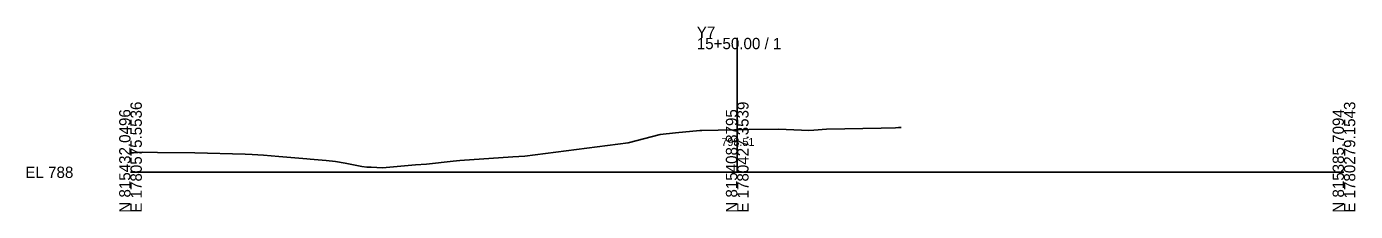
# Model space of a CAD drawing. Extents: x -26 to 2903, y -10 to 5536.
# Drawn here: x -25.7 to 302.8, y 5490.3 to 5536.1 of the extents above; entities that cross this region are included whole.
import ezdxf

# ---------------------------------------------------------------- set-up
doc = ezdxf.new("R2010")
doc.units = 0
for name, color, linetype in [('Exist Cross Section Cell', 7, 'Continuous'), ('Exist XS Center Line Elevation Label', 7, 'Continuous'), ('Exist XS Ground Line', 7, 'Continuous')]:
    doc.layers.add(name, color=color, linetype=linetype)

msp = doc.modelspace()

# ---------------------------------------------------------------- linework, layer by layer
at = {"layer": 'Exist Cross Section Cell'}
for p, q in [((150, 5500), (150, 5533.26)), ((0, 5500), (150, 5500)), ((150, 5500), (300, 5500))]:
    msp.add_line(p, q, dxfattribs=at)
at = {"layer": 'Exist XS Ground Line'}
for p, q in [((130.98, 5509.33), (134.78, 5509.72)), ((134.78, 5509.72), (140.78, 5510.31)), ((140.78, 5510.31), (141.25, 5510.32)), ((141.25, 5510.32), (149.33, 5510.5)), ((149.33, 5510.5), (150, 5510.51)), ((150, 5510.51), (152.87, 5510.55)), ((152.87, 5510.55), (160.24, 5510.68)), ((160.24, 5510.68), (165.92, 5510.38)), ((165.92, 5510.38), (167.67, 5510.37)), ((167.67, 5510.37), (168.93, 5510.39)), ((168.93, 5510.39), (172.09, 5510.69)), ((172.09, 5510.69), (185.55, 5510.89)), ((185.55, 5510.89), (189.12, 5511.03)), ((189.12, 5511.03), (189.85, 5511.06)), ((189.85, 5511.06), (190.54, 5511.09)), ((97.53, 5503.99), (123.01, 5507.3)), ((123.01, 5507.3), (130.98, 5509.33)), ((0, 5504.8), (0.76, 5504.84)), ((0.76, 5504.84), (2.92, 5504.94)), ((2.92, 5504.94), (6.71, 5504.9)), ((6.71, 5504.9), (15.94, 5504.78)), ((15.94, 5504.78), (28.34, 5504.5)), ((28.34, 5504.5), (30.08, 5504.41)), ((30.08, 5504.41), (32.88, 5504.25)), ((32.88, 5504.25), (36.64, 5503.94)), ((36.64, 5503.94), (43.61, 5503.34)), ((43.61, 5503.34), (44.44, 5503.27)), ((44.44, 5503.27), (48.34, 5502.89)), ((79.8, 5502.72), (81.43, 5502.93)), ((81.43, 5502.93), (94.51, 5503.86)), ((94.51, 5503.86), (97.53, 5503.99)), ((48.34, 5502.89), (50.67, 5502.66)), ((50.67, 5502.66), (53.09, 5502.23)), ((53.09, 5502.23), (57.21, 5501.46)), ((57.21, 5501.46), (58.39, 5501.24)), ((58.39, 5501.24), (59.49, 5501.23)), ((59.49, 5501.23), (62.33, 5501.13)), ((62.33, 5501.13), (70.47, 5501.82)), ((70.47, 5501.82), (73.14, 5502.04)), ((73.14, 5502.04), (79.8, 5502.72))]:
    msp.add_line(p, q, dxfattribs=at)

# ---------------------------------------------------------------- texts
at = {"layer": 'Exist Cross Section Cell'}
for s, p in [('Y7', (140, 5533.26)), ('15+50.00 / 1', (140, 5530.46)), ('EL 788', (-26, 5498.6))]:
    msp.add_text(s, height=2.8, dxfattribs=at).set_placement(p)
for s, p in [('E 1780575.5536', (2.8, 5490)), ('E 1780427.3539', (152.8, 5490)), ('E 1780279.1543', (302.8, 5490)), ('N 815432.0496', (0, 5490)), ('N 815408.8795', (150, 5490)), ('N 815385.7094', (300, 5490))]:
    msp.add_text(s, height=2.8, rotation=90, dxfattribs=at).set_placement(p)
at = {"layer": 'Exist XS Center Line Elevation Label'}
msp.add_text('798.51', height=2, dxfattribs=at).set_placement((146.08, 5506.51))

doc.saveas('drawing.dxf')
